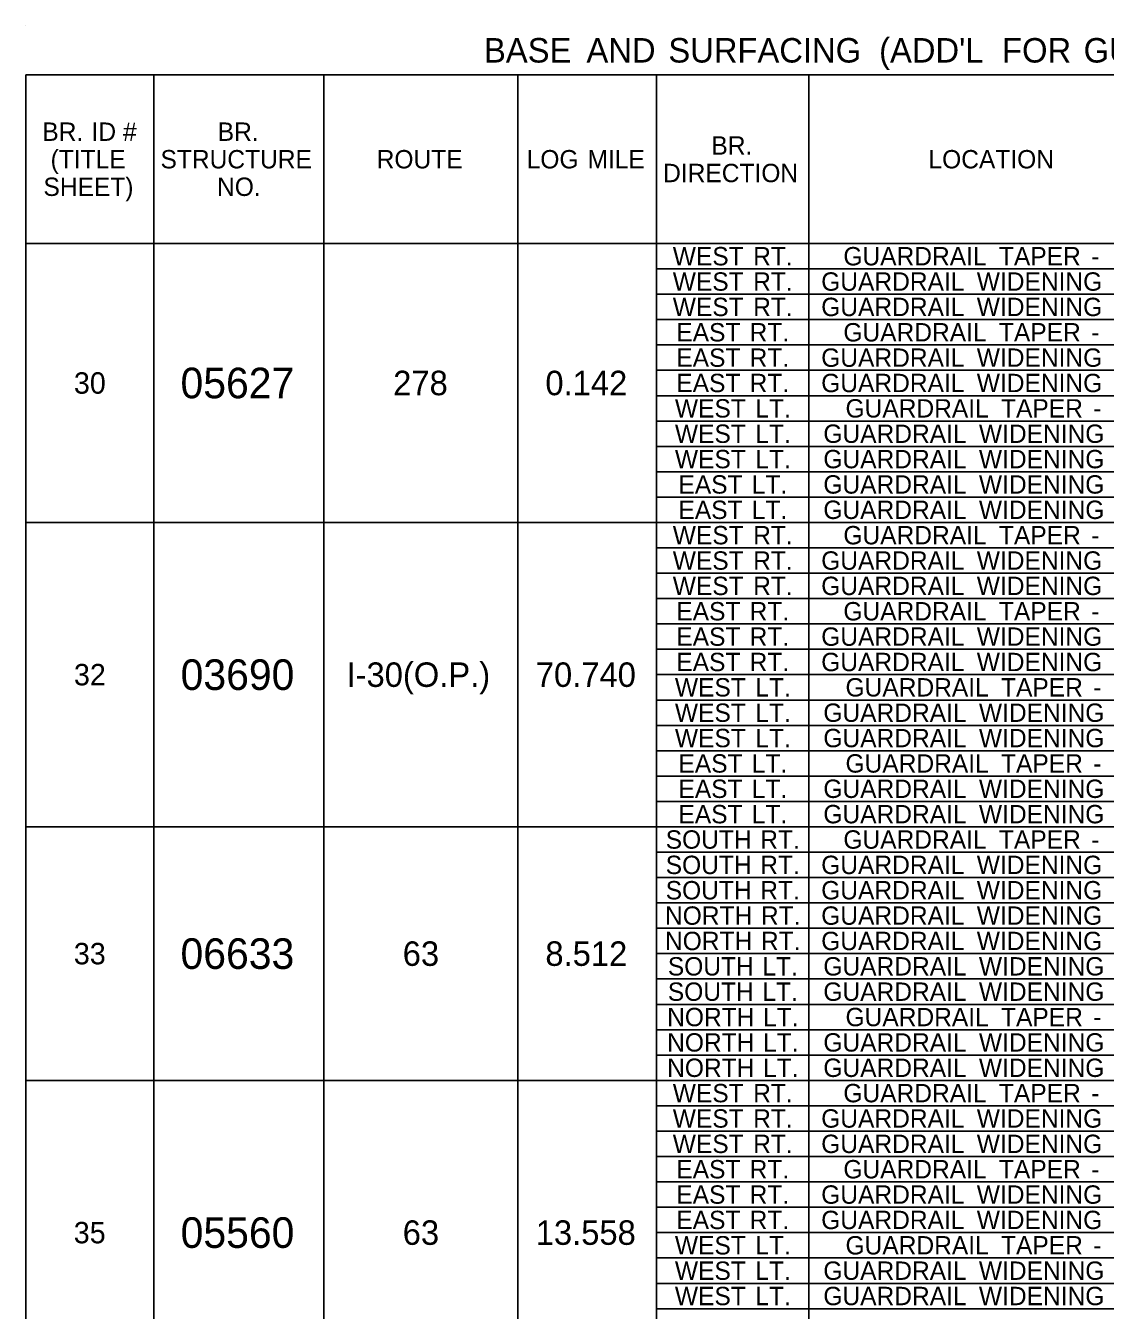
# Model space of a CAD drawing. Extents: x 544250 to 1930787, y -1948365 to 596640.
# Drawn here: x 544250.4 to 544603.2, y -1947785.2 to -1947365.4 of the extents above; entities that cross this region are included whole.
import ezdxf

# ---------------------------------------------------------------- set-up
doc = ezdxf.new("R2010")
doc.units = 0
doc.layers.add('Default', color=7, linetype='Continuous')

msp = doc.modelspace()

# ---------------------------------------------------------------- linework, layer by layer
at = {"layer": 'Default'}
for p, q in [((544250.37, -1947365.4), (544250.37, -1947365.4)), ((544250.37, -1947381.48), (544933.36, -1947381.48)), ((544250.37, -1948151.25), (544250.37, -1947381.48)), ((544292.29, -1948140.52), (544292.29, -1947381.48)), ((544347.87, -1948140.52), (544347.87, -1947381.48)), ((544411.24, -1948140.52), (544411.24, -1947381.48)), ((544456.58, -1948140.52), (544456.58, -1947381.48)), ((544506.31, -1948140.52), (544506.31, -1947381.48)), ((544250.37, -1947436.57), (544933.36, -1947436.57)), ((544456.58, -1947444.86), (544933.36, -1947444.86)), ((544456.58, -1947453.15), (544933.36, -1947453.15)), ((544456.58, -1947461.43), (544933.36, -1947461.43)), ((544456.58, -1947469.72), (544933.36, -1947469.72)), ((544456.58, -1947478.01), (544933.36, -1947478.01)), ((544456.58, -1947486.3), (544933.36, -1947486.3)), ((544456.58, -1947494.58), (544933.36, -1947494.58)), ((544456.58, -1947502.87), (544933.36, -1947502.87)), ((544456.58, -1947511.16), (544933.36, -1947511.16)), ((544456.58, -1947519.45), (544933.36, -1947519.45)), ((544250.37, -1947527.73), (544933.36, -1947527.73)), ((544456.58, -1947536.02), (544933.36, -1947536.02)), ((544456.58, -1947544.31), (544933.36, -1947544.31)), ((544456.58, -1947552.6), (544933.36, -1947552.6)), ((544456.58, -1947560.88), (544933.36, -1947560.88)), ((544456.58, -1947569.17), (544933.36, -1947569.17)), ((544456.58, -1947577.46), (544933.36, -1947577.46)), ((544456.58, -1947585.75), (544933.36, -1947585.75)), ((544456.58, -1947594.03), (544933.36, -1947594.03)), ((544456.58, -1947602.32), (544933.36, -1947602.32)), ((544456.58, -1947610.61), (544933.36, -1947610.61)), ((544456.58, -1947618.9), (544933.36, -1947618.9)), ((544250.37, -1947627.18), (544933.36, -1947627.18)), ((544456.58, -1947635.47), (544933.36, -1947635.47)), ((544456.58, -1947643.76), (544933.36, -1947643.76)), ((544456.58, -1947652.05), (544933.36, -1947652.05)), ((544456.58, -1947660.33), (544933.36, -1947660.33)), ((544456.58, -1947668.62), (544933.36, -1947668.62)), ((544456.58, -1947676.91), (544933.36, -1947676.91)), ((544456.58, -1947685.2), (544933.36, -1947685.2)), ((544456.58, -1947693.48), (544933.36, -1947693.48)), ((544456.58, -1947701.77), (544933.36, -1947701.77)), ((544250.37, -1947710.06), (544933.36, -1947710.06)), ((544456.58, -1947718.35), (544933.36, -1947718.35)), ((544456.58, -1947726.63), (544933.36, -1947726.63)), ((544456.58, -1947734.92), (544933.36, -1947734.92)), ((544456.58, -1947743.21), (544933.36, -1947743.21)), ((544456.58, -1947751.5), (544933.36, -1947751.5)), ((544456.58, -1947759.78), (544933.36, -1947759.78)), ((544456.58, -1947768.07), (544933.36, -1947768.07)), ((544456.58, -1947776.36), (544933.36, -1947776.36)), ((544456.58, -1947784.65), (544933.36, -1947784.65))]:
    msp.add_line(p, q, dxfattribs=at)

# ---------------------------------------------------------------- texts
for s, height, p in [('BASE', 8, (544400.18, -1947377.44)), (' AND', 8, (544430.69, -1947377.44)), (' SURFACING', 8, (544457.46, -1947377.44)), (" (ADD'L", 8, (544526.34, -1947377.44)), (' FOR', 8, (544566.53, -1947377.44)), (' GUARDRAIL)', 8, (544593.18, -1947377.44)), ('BR.', 6, (544255.81, -1947403.03)), (' ID', 6, (544269.67, -1947403.03)), (' #', 6, (544279.96, -1947403.03)), ('BR.', 6, (544313.15, -1947403.03)), ('BR.', 6, (544474.51, -1947407.53)), ('(TITLE', 6, (544258.5, -1947412.03)), ('STRUCTURE', 6, (544294.44, -1947412.03)), ('ROUTE', 6, (544365.09, -1947412.03)), ('LOG', 6, (544414.12, -1947412.03)), (' MILE', 6, (544431.77, -1947412.03)), ('LOCATION', 6, (544545.45, -1947412.03)), ('DIRECTION', 6, (544458.72, -1947416.53)), ('SHEET)', 6, (544256.18, -1947421.03)), ('NO.', 6, (544312.92, -1947421.03)), ('WEST', 6, (544461.87, -1947443.72)), (' RT.', 6, (544485.92, -1947443.72)), ('GUARDRAIL', 6, (544517.63, -1947443.72)), (' TAPER', 6, (544566.25, -1947443.72)), (' -', 6, (544596.41, -1947443.72)), ('WEST', 6, (544461.87, -1947452)), (' RT.', 6, (544485.92, -1947452)), ('GUARDRAIL', 6, (544510.39, -1947452)), (' WIDENING', 6, (544559.01, -1947452)), ('WEST', 6, (544461.87, -1947460.29)), (' RT.', 6, (544485.92, -1947460.29)), ('GUARDRAIL', 6, (544510.39, -1947460.29)), (' WIDENING', 6, (544559.01, -1947460.29)), ('EAST', 6, (544463.03, -1947468.58)), (' RT.', 6, (544484.76, -1947468.58)), ('GUARDRAIL', 6, (544517.63, -1947468.58)), (' TAPER', 6, (544566.25, -1947468.58)), (' -', 6, (544596.41, -1947468.58)), ('EAST', 6, (544463.03, -1947476.87)), (' RT.', 6, (544484.76, -1947476.87)), ('GUARDRAIL', 6, (544510.39, -1947476.87)), (' WIDENING', 6, (544559.01, -1947476.87)), ('30', 7, (544266.13, -1947485.65)), ('05627', 10, (544300.97, -1947487.15)), ('278', 8, (544370.48, -1947486.15)), ('0.142', 8, (544420.23, -1947486.15)), ('EAST', 6, (544463.03, -1947485.15)), (' RT.', 6, (544484.76, -1947485.15)), ('GUARDRAIL', 6, (544510.39, -1947485.15)), (' WIDENING', 6, (544559.01, -1947485.15)), ('WEST', 6, (544462.57, -1947493.44)), (' LT.', 6, (544486.62, -1947493.44)), ('GUARDRAIL', 6, (544518.33, -1947493.44)), (' TAPER', 6, (544566.94, -1947493.44)), (' -', 6, (544597.11, -1947493.44)), ('WEST', 6, (544462.57, -1947501.73)), (' LT.', 6, (544486.62, -1947501.73)), ('GUARDRAIL', 6, (544511.09, -1947501.73)), (' WIDENING', 6, (544559.7, -1947501.73)), ('WEST', 6, (544462.57, -1947510.02)), (' LT.', 6, (544486.62, -1947510.02)), ('GUARDRAIL', 6, (544511.09, -1947510.02)), (' WIDENING', 6, (544559.7, -1947510.02)), ('EAST', 6, (544463.73, -1947518.3)), (' LT.', 6, (544485.46, -1947518.3)), ('GUARDRAIL', 6, (544511.09, -1947518.3)), (' WIDENING', 6, (544559.7, -1947518.3)), ('EAST', 6, (544463.73, -1947526.59)), (' LT.', 6, (544485.46, -1947526.59)), ('GUARDRAIL', 6, (544511.09, -1947526.59)), (' WIDENING', 6, (544559.7, -1947526.59)), ('WEST', 6, (544461.87, -1947534.88)), (' RT.', 6, (544485.92, -1947534.88)), ('GUARDRAIL', 6, (544517.63, -1947534.88)), (' TAPER', 6, (544566.25, -1947534.88)), (' -', 6, (544596.41, -1947534.88)), ('WEST', 6, (544461.87, -1947543.17)), (' RT.', 6, (544485.92, -1947543.17)), ('GUARDRAIL', 6, (544510.39, -1947543.17)), (' WIDENING', 6, (544559.01, -1947543.17)), ('WEST', 6, (544461.87, -1947551.45)), (' RT.', 6, (544485.92, -1947551.45)), ('GUARDRAIL', 6, (544510.39, -1947551.45)), (' WIDENING', 6, (544559.01, -1947551.45)), ('EAST', 6, (544463.03, -1947559.74)), (' RT.', 6, (544484.76, -1947559.74)), ('GUARDRAIL', 6, (544517.63, -1947559.74)), (' TAPER', 6, (544566.25, -1947559.74)), (' -', 6, (544596.41, -1947559.74)), ('EAST', 6, (544463.03, -1947568.03)), (' RT.', 6, (544484.76, -1947568.03)), ('GUARDRAIL', 6, (544510.39, -1947568.03)), (' WIDENING', 6, (544559.01, -1947568.03)), ('03690', 10, (544301.01, -1947582.46)), ('EAST', 6, (544463.03, -1947576.32)), (' RT.', 6, (544484.76, -1947576.32)), ('GUARDRAIL', 6, (544510.39, -1947576.32)), (' WIDENING', 6, (544559.01, -1947576.32)), ('32', 7, (544266.15, -1947580.96)), ('I-30(O.P.)', 8, (544355.23, -1947581.46)), ('70.740', 8, (544417.1, -1947581.46)), ('WEST', 6, (544462.57, -1947584.6)), (' LT.', 6, (544486.62, -1947584.6)), ('GUARDRAIL', 6, (544518.33, -1947584.6)), (' TAPER', 6, (544566.94, -1947584.6)), (' -', 6, (544597.11, -1947584.6)), ('WEST', 6, (544462.57, -1947592.89)), (' LT.', 6, (544486.62, -1947592.89)), ('GUARDRAIL', 6, (544511.09, -1947592.89)), (' WIDENING', 6, (544559.7, -1947592.89)), ('WEST', 6, (544462.57, -1947601.18)), (' LT.', 6, (544486.62, -1947601.18)), ('GUARDRAIL', 6, (544511.09, -1947601.18)), (' WIDENING', 6, (544559.7, -1947601.18)), ('EAST', 6, (544463.73, -1947609.47)), (' LT.', 6, (544485.46, -1947609.47)), ('GUARDRAIL', 6, (544518.33, -1947609.47)), (' TAPER', 6, (544566.94, -1947609.47)), (' -', 6, (544597.11, -1947609.47)), ('EAST', 6, (544463.73, -1947617.75)), (' LT.', 6, (544485.46, -1947617.75)), ('GUARDRAIL', 6, (544511.09, -1947617.75)), (' WIDENING', 6, (544559.7, -1947617.75)), ('EAST', 6, (544463.73, -1947626.04)), (' LT.', 6, (544485.46, -1947626.04)), ('GUARDRAIL', 6, (544511.09, -1947626.04)), (' WIDENING', 6, (544559.7, -1947626.04)), ('SOUTH', 6, (544459.56, -1947634.33)), (' RT.', 6, (544488.23, -1947634.33)), ('GUARDRAIL', 6, (544517.63, -1947634.33)), (' TAPER', 6, (544566.25, -1947634.33)), (' -', 6, (544596.41, -1947634.33)), ('SOUTH', 6, (544459.56, -1947642.62)), (' RT.', 6, (544488.23, -1947642.62)), ('GUARDRAIL', 6, (544510.39, -1947642.62)), (' WIDENING', 6, (544559.01, -1947642.62)), ('SOUTH', 6, (544459.56, -1947650.9)), (' RT.', 6, (544488.23, -1947650.9)), ('GUARDRAIL', 6, (544510.39, -1947650.9)), (' WIDENING', 6, (544559.01, -1947650.9)), ('NORTH', 6, (544459.33, -1947659.19)), (' RT.', 6, (544488.46, -1947659.19)), ('GUARDRAIL', 6, (544510.39, -1947659.19)), (' WIDENING', 6, (544559.01, -1947659.19)), ('33', 7, (544266.12, -1947672.12)), ('06633', 10, (544300.97, -1947673.62)), ('63', 8, (544373.6, -1947672.62)), ('8.512', 8, (544420.23, -1947672.62)), ('NORTH', 6, (544459.33, -1947667.48)), (' RT.', 6, (544488.46, -1947667.48)), ('GUARDRAIL', 6, (544510.39, -1947667.48)), (' WIDENING', 6, (544559.01, -1947667.48)), ('SOUTH', 6, (544460.26, -1947675.77)), (' LT.', 6, (544488.93, -1947675.77)), ('GUARDRAIL', 6, (544511.09, -1947675.77)), (' WIDENING', 6, (544559.7, -1947675.77)), ('SOUTH', 6, (544460.26, -1947684.05)), (' LT.', 6, (544488.93, -1947684.05)), ('GUARDRAIL', 6, (544511.09, -1947684.05)), (' WIDENING', 6, (544559.7, -1947684.05)), ('NORTH', 6, (544460.03, -1947692.34)), ('GUARDRAIL', 6, (544518.33, -1947692.34)), (' LT.', 6, (544489.16, -1947692.34)), (' TAPER', 6, (544566.94, -1947692.34)), (' -', 6, (544597.11, -1947692.34)), ('NORTH', 6, (544460.03, -1947700.63)), (' LT.', 6, (544489.16, -1947700.63)), ('GUARDRAIL', 6, (544511.09, -1947700.63)), (' WIDENING', 6, (544559.7, -1947700.63)), ('NORTH', 6, (544460.03, -1947708.92)), (' LT.', 6, (544489.16, -1947708.92)), ('GUARDRAIL', 6, (544511.09, -1947708.92)), (' WIDENING', 6, (544559.7, -1947708.92)), ('WEST', 6, (544461.87, -1947717.2)), (' RT.', 6, (544485.92, -1947717.2)), ('GUARDRAIL', 6, (544517.63, -1947717.2)), (' TAPER', 6, (544566.25, -1947717.2)), (' -', 6, (544596.41, -1947717.2)), ('WEST', 6, (544461.87, -1947725.49)), (' RT.', 6, (544485.92, -1947725.49)), ('GUARDRAIL', 6, (544510.39, -1947725.49)), (' WIDENING', 6, (544559.01, -1947725.49)), ('WEST', 6, (544461.87, -1947733.78)), (' RT.', 6, (544485.92, -1947733.78)), ('GUARDRAIL', 6, (544510.39, -1947733.78)), (' WIDENING', 6, (544559.01, -1947733.78)), ('EAST', 6, (544463.03, -1947742.07)), (' RT.', 6, (544484.76, -1947742.07)), ('GUARDRAIL', 6, (544517.63, -1947742.07)), (' TAPER', 6, (544566.25, -1947742.07)), (' -', 6, (544596.41, -1947742.07)), ('EAST', 6, (544463.03, -1947750.35)), (' RT.', 6, (544484.76, -1947750.35)), ('GUARDRAIL', 6, (544510.39, -1947750.35)), (' WIDENING', 6, (544559.01, -1947750.35)), ('EAST', 6, (544463.03, -1947758.64)), (' RT.', 6, (544484.76, -1947758.64)), ('GUARDRAIL', 6, (544510.39, -1947758.64)), (' WIDENING', 6, (544559.01, -1947758.64)), ('35', 7, (544266.09, -1947763.28)), ('05560', 10, (544301.01, -1947764.78)), ('63', 8, (544373.6, -1947763.78)), ('13.558', 8, (544417.07, -1947763.78)), ('WEST', 6, (544462.57, -1947766.93)), (' LT.', 6, (544486.62, -1947766.93)), ('GUARDRAIL', 6, (544518.33, -1947766.93)), (' TAPER', 6, (544566.94, -1947766.93)), (' -', 6, (544597.11, -1947766.93)), ('WEST', 6, (544462.57, -1947775.22)), (' LT.', 6, (544486.62, -1947775.22)), ('GUARDRAIL', 6, (544511.09, -1947775.22)), (' WIDENING', 6, (544559.7, -1947775.22)), ('WEST', 6, (544462.57, -1947783.5)), (' LT.', 6, (544486.62, -1947783.5)), ('GUARDRAIL', 6, (544511.09, -1947783.5)), (' WIDENING', 6, (544559.7, -1947783.5))]:
    msp.add_text(s, height=height, dxfattribs=at).set_placement(p)

doc.saveas('drawing.dxf')
